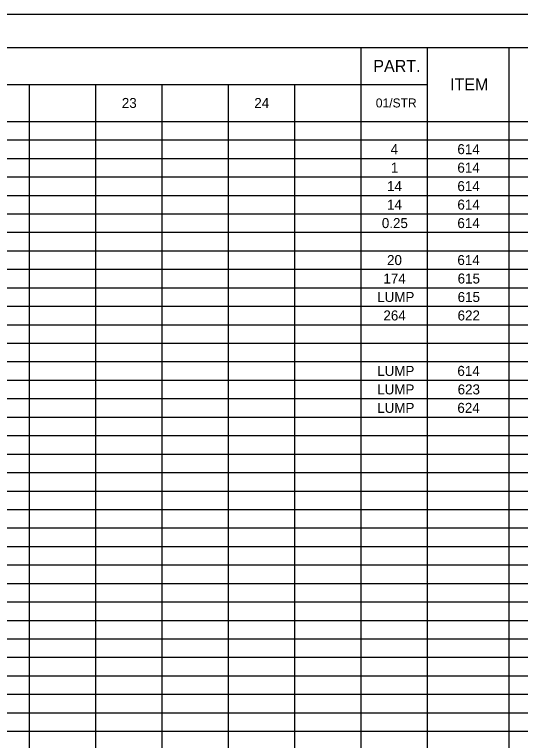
# Model space of a CAD drawing. Extents: x 0 to 34, y 0 to 22.
# Drawn here: x 9.32 to 16.98, y 11 to 22 of the extents above; entities that cross this region are included whole.
import ezdxf

# ---------------------------------------------------------------- set-up
doc = ezdxf.new("R2010")
doc.units = 0
for name, color, linetype in [('Default', 7, 'Continuous'), ('SH_Border', 7, 'Continuous'), ('SH_Cut_Line', 7, 'Continuous')]:
    doc.layers.add(name, color=color, linetype=linetype)

msp = doc.modelspace()

# ---------------------------------------------------------------- linework, layer by layer
at = {"layer": 'Default'}
for p, q in [((1.5, 21.5), (32.004, 21.5)), ((14.561, 21.5), (14.561, 0.5)), ((15.566, 21.5), (15.566, 0.5)), ((16.801, 21.5), (16.801, 0.5)), ((1.5, 20.94), (15.566, 20.94)), ((9.538, 20.94), (9.538, 0.5)), ((10.542, 20.94), (10.542, 0.5)), ((11.547, 20.94), (11.547, 0.5)), ((12.552, 20.94), (12.552, 0.5)), ((13.556, 20.94), (13.556, 0.5)), ((1.5, 20.38), (32.004, 20.38)), ((1.5, 20.1), (32.004, 20.1)), ((1.5, 19.82), (32.004, 19.82)), ((1.5, 19.54), (32.004, 19.54)), ((1.5, 19.26), (32.004, 19.26)), ((1.5, 18.98), (32.004, 18.98)), ((1.5, 18.7), (32.004, 18.7)), ((1.5, 18.42), (32.004, 18.42)), ((1.5, 18.14), (32.004, 18.14)), ((1.5, 17.86), (32.004, 17.86)), ((1.5, 17.58), (32.004, 17.58)), ((1.5, 17.3), (32.004, 17.3)), ((1.5, 17.02), (32.004, 17.02)), ((1.5, 16.74), (32.004, 16.74)), ((1.5, 16.46), (32.004, 16.46)), ((1.5, 16.18), (32.004, 16.18)), ((1.5, 15.9), (32.004, 15.9)), ((1.5, 15.62), (32.004, 15.62)), ((1.5, 15.34), (32.004, 15.34)), ((1.5, 15.06), (32.004, 15.06)), ((1.5, 14.78), (32.004, 14.78)), ((1.5, 14.5), (32.004, 14.5)), ((1.5, 14.22), (32.004, 14.22)), ((1.5, 13.94), (32.004, 13.94)), ((1.5, 13.66), (32.004, 13.66)), ((1.5, 13.38), (32.004, 13.38)), ((1.5, 13.1), (32.004, 13.1)), ((1.5, 12.82), (32.004, 12.82)), ((1.5, 12.54), (32.004, 12.54)), ((1.5, 12.26), (32.004, 12.26)), ((1.5, 11.98), (32.004, 11.98)), ((1.5, 11.7), (32.004, 11.7)), ((1.5, 11.42), (32.004, 11.42)), ((1.5, 11.14), (32.004, 11.14))]:
    msp.add_line(p, q, dxfattribs=at)
at = {"layer": 'SH_Border'}
msp.add_lwpolyline([(1.5, 21.5), (33.5, 21.5), (33.5, 0.5), (1.5, 0.5)], close=True, dxfattribs=at)
at = {"layer": 'SH_Cut_Line'}
msp.add_lwpolyline([(0, 0), (34, 0), (34, 22), (0, 22)], close=True, dxfattribs=at)

# ---------------------------------------------------------------- texts
at = {"layer": 'Default'}
for s, height, p in [('PART.', 0.1818, (14.75, 21.129)), ('ITEM', 0.1818, (15.912, 20.849)), ('23', 0.1515, (10.942, 20.584)), ('24', 0.1515, (12.948, 20.584)), ('01/STR', 0.1364, (14.788, 20.592)), ('4', 0.152, (15.012, 19.884)), ('614', 0.1515, (16.023, 19.884)), ('1', 0.152, (15.015, 19.604)), ('614', 0.1515, (16.023, 19.604)), ('14', 0.1515, (14.958, 19.324)), ('614', 0.1515, (16.023, 19.324)), ('14', 0.1515, (14.958, 19.044)), ('614', 0.1515, (16.023, 19.044)), ('0.25', 0.1515, (14.879, 18.764)), ('614', 0.1515, (16.023, 18.764)), ('20', 0.1515, (14.958, 18.204)), ('614', 0.1515, (16.023, 18.204)), ('174', 0.1515, (14.903, 17.924)), ('615', 0.1515, (16.027, 17.924)), ('LUMP', 0.1515, (14.809, 17.644)), ('615', 0.1515, (16.027, 17.644)), ('264', 0.1515, (14.903, 17.364)), ('622', 0.1515, (16.026, 17.364)), ('LUMP', 0.1515, (14.809, 16.524)), ('614', 0.1515, (16.023, 16.524)), ('LUMP', 0.1515, (14.809, 16.244)), ('623', 0.1515, (16.027, 16.244)), ('LUMP', 0.1515, (14.809, 15.964)), ('624', 0.1515, (16.023, 15.964))]:
    msp.add_text(s, height=height, dxfattribs=at).set_placement(p)

doc.saveas('drawing.dxf')
